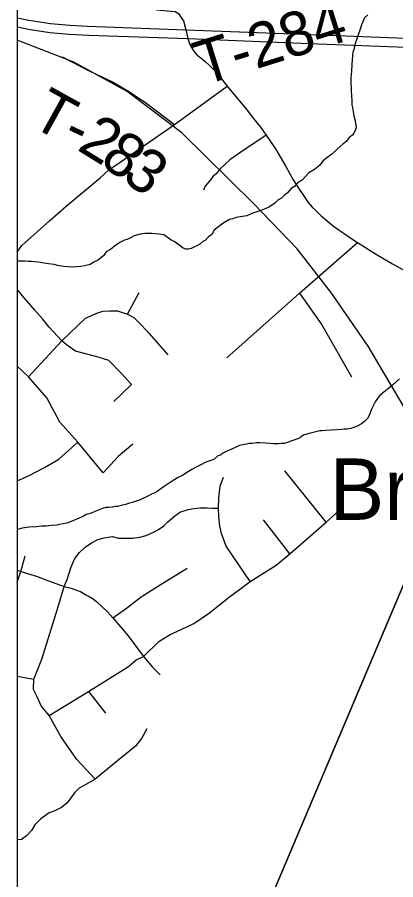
# Model space of a CAD drawing. Extents: x 0 to 34, y 0 to 22.
# Drawn here: x 2.1 to 2.587, y 16.889 to 17.998 of the extents above; entities that cross this region are included whole.
import ezdxf

# ---------------------------------------------------------------- set-up
doc = ezdxf.new("R2010")
doc.units = 0
for name, color, linetype in [('GM_X_Corporation', 7, 'Continuous'), ('GM_X_County_Road', 7, 'Continuous'), ('GM_X_Minor_River', 7, 'Continuous'), ('GM_X_Rail_Line', 7, 'Continuous'), ('GM_X_State_Route', 7, 'Continuous'), ('GM_X_Township_Road', 7, 'Continuous'), ('GM_X_Township_Road_Text', 7, 'Continuous'), ('GM_X_Unincorporated_Text', 7, 'Continuous'), ('SH_Data', 7, 'Continuous')]:
    doc.layers.add(name, color=color, linetype=linetype)

msp = doc.modelspace()

# ---------------------------------------------------------------- linework, layer by layer
at = {"layer": 'GM_X_Corporation'}
for points in [[(2.1, 20.9), (2.1, 16.0934), (2.225, 16.3897), (2.7544, 17.639), (2.811, 17.7726), (2.8255, 17.8068), (2.8709, 17.914), (2.886, 17.9497), (2.8909, 17.9612), (2.9719, 18.1533), (3.7872, 20.088)], [(3.7872, 20.088), (2.9719, 18.1533), (2.8909, 17.9612), (2.886, 17.9497), (2.8709, 17.914), (2.8255, 17.8068), (2.811, 17.7726), (2.7544, 17.639), (2.225, 16.3897), (2.1, 16.0934), (2.1, 14.8365)]]:
    msp.add_lwpolyline(points, dxfattribs=at)
at = {"layer": 'GM_X_County_Road'}
for points in [[(2.1, 18.1121), (2.1218, 18.0985), (2.1562, 18.078), (2.175, 18.0677), (2.2185, 18.0405), (2.228, 18.0349), (2.254, 18.0195), (2.2625, 18.0135), (2.2717, 18.0099), (2.2803, 18.0077), (2.2932, 18.0068), (2.3031, 18.0057), (2.3077, 18.003), (2.3108, 17.9984), (2.314, 17.9938), (2.3172, 17.982), (2.3194, 17.9708)], [(2.3194, 17.9708), (2.3223, 17.9635), (2.3268, 17.9553), (2.3316, 17.9497), (2.3364, 17.9461), (2.3421, 17.9413), (2.3481, 17.9359), (2.3564, 17.9272), (2.3702, 17.9096), (2.3956, 17.8794), (2.4037, 17.8686), (2.413, 17.8569), (2.4205, 17.8468), (2.4324, 17.8291), (2.4456, 17.8064), (2.4552, 17.7893), (2.463, 17.7772), (2.4695, 17.7676), (2.4747, 17.7598), (2.4797, 17.7538), (2.4841, 17.7501), (2.4911, 17.7429), (2.4994, 17.7358), (2.5073, 17.7294), (2.5144, 17.7244), (2.521, 17.7202), (2.5296, 17.7142), (2.538, 17.7083), (2.5633, 17.6925), (2.583, 17.6811), (2.5987, 17.6725)], [(2.1415, 17.7363), (2.1628, 17.7552), (2.2066, 17.7916), (2.2179, 17.8019), (2.2326, 17.8118), (2.3026, 17.8605), (2.3702, 17.9096)], [(2.1, 17.6961), (2.1058, 17.7046), (2.1415, 17.7363)]]:
    msp.add_lwpolyline(points, dxfattribs=at)
at = {"layer": 'GM_X_Minor_River'}
for points in [[(2.5515, 18.0015), (2.5472, 17.9974), (2.5433, 17.9887), (2.5413, 17.9831), (2.5389, 17.9759), (2.536, 17.9668), (2.5341, 17.9619), (2.5336, 17.9577), (2.532, 17.9535), (2.5311, 17.9441), (2.5306, 17.9376), (2.5305, 17.9296), (2.53, 17.9243), (2.5296, 17.9209), (2.5294, 17.9121), (2.5297, 17.9079), (2.5297, 17.9045), (2.5303, 17.8961), (2.5306, 17.8923), (2.5309, 17.8855), (2.5316, 17.8824), (2.5323, 17.8771), (2.533, 17.874), (2.5337, 17.8698), (2.5347, 17.8668), (2.5358, 17.8599), (2.5361, 17.8561), (2.5345, 17.8516), (2.5317, 17.8467), (2.5279, 17.8441), (2.5236, 17.8384), (2.519, 17.8351), (2.512, 17.8284), (2.5051, 17.822), (2.497, 17.8161), (2.4932, 17.8131), (2.4893, 17.8075), (2.4827, 17.8023), (2.4754, 17.7982), (2.4669, 17.7889), (2.4611, 17.7859), (2.4569, 17.7807), (2.4526, 17.7781), (2.4476, 17.7721), (2.4441, 17.7695), (2.4403, 17.7657), (2.436, 17.7632)], [(2.436, 17.7632), (2.4318, 17.759), (2.4249, 17.7546), (2.4191, 17.7517), (2.4134, 17.7495), (2.4084, 17.748), (2.4042, 17.7466), (2.3954, 17.7429), (2.387, 17.7416), (2.3817, 17.7405), (2.3775, 17.7391), (2.3733, 17.738), (2.366, 17.7339), (2.3629, 17.7317), (2.3575, 17.7273), (2.3536, 17.7243), (2.3505, 17.7186), (2.3463, 17.716), (2.342, 17.7112), (2.339, 17.7097), (2.3347, 17.706), (2.324, 17.7008), (2.3205, 17.6998), (2.3171, 17.6998), (2.3137, 17.701), (2.3096, 17.7041), (2.3021, 17.71), (2.2983, 17.7116), (2.2919, 17.7162), (2.2889, 17.7182), (2.2832, 17.7194), (2.2734, 17.72), (2.2642, 17.7201), (2.2581, 17.7191), (2.2505, 17.717), (2.2467, 17.7151), (2.2417, 17.7125), (2.2382, 17.7115), (2.2329, 17.7089), (2.2275, 17.7056), (2.2202, 17.6996), (2.2144, 17.6963), (2.2109, 17.6914), (2.2074, 17.6888), (2.2044, 17.6862), (2.1986, 17.6833), (2.194, 17.6803), (2.1867, 17.6785), (2.1818, 17.6775), (2.1761, 17.6772), (2.1715, 17.6769), (2.1658, 17.677), (2.1597, 17.6778), (2.1518, 17.6787), (2.1476, 17.68), (2.1404, 17.6812), (2.1347, 17.6821), (2.1275, 17.683), (2.1218, 17.6835), (2.1184, 17.6839), (2.1142, 17.684), (2.1097, 17.6844), (2.1059, 17.6845), (2.1, 17.6843)], [(2.5922, 17.533), (2.583, 17.5248), (2.5783, 17.5211), (2.5699, 17.5144), (2.5664, 17.511), (2.5637, 17.5076), (2.5609, 17.5035), (2.5586, 17.499), (2.5562, 17.4941), (2.5542, 17.4892), (2.553, 17.4861), (2.5511, 17.482), (2.5472, 17.4783), (2.543, 17.4753), (2.5376, 17.472), (2.5322, 17.4701), (2.5292, 17.4691), (2.5246, 17.4684), (2.5208, 17.4681), (2.5174, 17.4677), (2.5117, 17.4675), (2.5041, 17.4672), (2.4972, 17.4666), (2.4926, 17.4663), (2.4896, 17.4663), (2.4842, 17.4649), (2.4758, 17.4628), (2.4686, 17.4606), (2.464, 17.4573), (2.4598, 17.4554), (2.4536, 17.4533), (2.4479, 17.4511), (2.4437, 17.45), (2.4399, 17.4497), (2.4365, 17.4494), (2.43, 17.4495), (2.4254, 17.45), (2.4201, 17.4501), (2.4121, 17.4506)], [(2.4121, 17.4506), (2.408, 17.4506), (2.4023, 17.45), (2.3984, 17.4497), (2.395, 17.449), (2.3862, 17.4472), (2.3778, 17.4436), (2.369, 17.4395), (2.3648, 17.4373), (2.3617, 17.4347), (2.3583, 17.434), (2.3529, 17.4292), (2.3429, 17.4259), (2.3364, 17.4226), (2.3303, 17.4193), (2.3249, 17.4163), (2.3191, 17.413), (2.313, 17.4093), (2.3065, 17.4056), (2.2995, 17.4016), (2.2942, 17.3979), (2.2892, 17.3945), (2.2849, 17.3916), (2.2803, 17.3882), (2.2772, 17.3864), (2.273, 17.3846), (2.268, 17.382), (2.2581, 17.3772), (2.2543, 17.3761), (2.2481, 17.374), (2.2447, 17.3729), (2.2394, 17.3714), (2.2336, 17.37), (2.229, 17.369), (2.2256, 17.3686), (2.2226, 17.3679), (2.2176, 17.3676), (2.2142, 17.3673), (2.2096, 17.3663), (2.1989, 17.3619), (2.1951, 17.3604), (2.192, 17.3593), (2.1886, 17.3583), (2.1851, 17.3564), (2.1797, 17.3539), (2.1744, 17.3517), (2.1694, 17.3495), (2.164, 17.3473), (2.1564, 17.3459), (2.1511, 17.3449), (2.1435, 17.3442), (2.1378, 17.3436), (2.1317, 17.3433), (2.1244, 17.3427), (2.1153, 17.3421), (2.1062, 17.3411), (2.1004, 17.3393), (2.1, 17.3392)]]:
    msp.add_lwpolyline(points, dxfattribs=at)
at = {"layer": 'GM_X_Rail_Line'}
msp.add_lwpolyline([(2.7988, 17.139), (2.7752, 17.2035), (2.7136, 17.3012), (2.6321, 17.4391), (2.5518, 17.5749), (2.5037, 17.6444), (2.4602, 17.7003), (2.4041, 17.7589), (2.312, 17.8497), (2.2416, 17.9026), (2.1727, 17.9405), (2.1, 17.969)], dxfattribs=at)
at = {"layer": 'GM_X_State_Route'}
for points in [[(2.1, 17.9977), (2.1151, 17.9948), (2.1428, 17.9904), (2.1678, 17.9882), (2.1903, 17.987), (2.3172, 17.982), (2.4779, 17.976), (2.6115, 17.971), (2.8441, 17.9625), (2.8912, 17.9607), (2.9371, 17.959)], [(2.1, 17.9859), (2.1143, 17.9832), (2.1419, 17.9788), (2.1669, 17.9766), (2.1921, 17.9753), (2.3194, 17.9708), (2.4757, 17.9644), (2.6117, 17.9593), (2.8442, 17.9508), (2.8492, 17.9506)]]:
    msp.add_lwpolyline(points, dxfattribs=at)
at = {"layer": 'GM_X_Township_Road'}
for p, q in [((2.2421, 17.6165), (2.257, 17.6443)), ((2.1145, 17.5357), (2.1, 17.5494)), ((2.4975, 17.3488), (2.4446, 17.4146)), ((2.451, 17.3079), (2.4172, 17.3515)), ((2.1, 17.1505), (2.1212, 17.1467)), ((2.1916, 17.1309), (2.2135, 17.103))]:
    msp.add_line(p, q, dxfattribs=at)
for points in [[(2.1578, 17.9473), (2.1925, 17.9293), (2.2236, 17.9147), (2.2443, 17.9024), (2.267, 17.8874), (2.3026, 17.8605)], [(2.4205, 17.8468), (2.3877, 17.8248), (2.3735, 17.8147), (2.3605, 17.8025), (2.3578, 17.7991)], [(2.3578, 17.7991), (2.3561, 17.797), (2.352, 17.7934), (2.3493, 17.7895), (2.3419, 17.7812), (2.3399, 17.7757)], [(2.3698, 17.5602), (2.4632, 17.6434), (2.538, 17.7083)], [(2.1068, 17.6399), (2.1012, 17.6466), (2.1, 17.6479)], [(2.2245, 17.5038), (2.2471, 17.5258), (2.2347, 17.5393), (2.2178, 17.5565), (2.2042, 17.5608), (2.1831, 17.5665), (2.1752, 17.5686), (2.1632, 17.5767), (2.1572, 17.582), (2.1412, 17.5995), (2.1324, 17.6102), (2.1225, 17.6215), (2.1068, 17.6399)], [(2.4632, 17.6434), (2.4921, 17.6025), (2.5304, 17.5355)], [(2.1145, 17.5357), (2.1572, 17.582), (2.188, 17.6113), (2.2025, 17.6176), (2.2102, 17.6201), (2.2193, 17.6206), (2.229, 17.6206), (2.2421, 17.6165), (2.25, 17.612), (2.2602, 17.6018), (2.2697, 17.5914), (2.2937, 17.564)], [(2.249, 17.4489), (2.2299, 17.4332), (2.2108, 17.4123), (2.1779, 17.4516), (2.155, 17.4771), (2.1379, 17.5088), (2.1145, 17.5357)], [(2.1, 17.4017), (2.1145, 17.4081), (2.1352, 17.4191), (2.1536, 17.4295), (2.1779, 17.4516)], [(2.3999, 17.2721), (2.3688, 17.3179), (2.3631, 17.3341), (2.3607, 17.3441), (2.3593, 17.3557), (2.359, 17.3666), (2.3595, 17.3799), (2.3612, 17.3949), (2.3657, 17.4067)], [(2.2004, 17.0178), (2.1766, 17.0434), (2.1561, 17.0727), (2.1409, 17.0998), (2.131, 17.1125), (2.1255, 17.1238), (2.121, 17.1334), (2.1212, 17.1467), (2.1318, 17.1725), (2.1524, 17.2383), (2.1606, 17.266), (2.1644, 17.2748), (2.1695, 17.291), (2.1743, 17.3019), (2.18, 17.3095), (2.1873, 17.3166), (2.1955, 17.3219), (2.2039, 17.3264), (2.2118, 17.3285), (2.222, 17.33), (2.2304, 17.3279), (2.2396, 17.3282), (2.2482, 17.3282), (2.2579, 17.3295), (2.266, 17.3316), (2.2753, 17.3359), (2.2818, 17.3393), (2.2888, 17.3439), (2.294, 17.3489), (2.3023, 17.3565), (2.3095, 17.3613), (2.32, 17.3649), (2.3275, 17.3663), (2.335, 17.3672), (2.3447, 17.367), (2.3512, 17.3665), (2.359, 17.3666)], [(2.1409, 17.0998), (2.1916, 17.1309), (2.2431, 17.1629), (2.2531, 17.1716), (2.2624, 17.1757), (2.2823, 17.195), (2.2967, 17.2041), (2.311, 17.2105), (2.3275, 17.2182), (2.3476, 17.2319), (2.3717, 17.2511), (2.3894, 17.2645), (2.3999, 17.2721), (2.4333, 17.2935), (2.451, 17.3079), (2.4975, 17.3488), (2.5183, 17.3671)], [(2.1, 17.2716), (2.1048, 17.2851), (2.1101, 17.3052)], [(2.1, 17.2868), (2.1048, 17.2851), (2.1133, 17.2825), (2.126, 17.2788), (2.1354, 17.2749), (2.1606, 17.266), (2.1696, 17.2636), (2.1752, 17.2617), (2.1814, 17.2594), (2.1885, 17.2551), (2.1924, 17.2529), (2.1978, 17.2498), (2.2025, 17.246), (2.2096, 17.2394), (2.2166, 17.2328), (2.223, 17.2255), (2.2426, 17.2025), (2.2624, 17.1757), (2.2743, 17.1622), (2.284, 17.152)], [(2.223, 17.2255), (2.2408, 17.2378), (2.2594, 17.2525), (2.2817, 17.2666), (2.3186, 17.2894)], [(2.267, 17.0827), (2.2601, 17.0704), (2.2523, 17.0604), (2.2223, 17.0358)], [(2.2223, 17.0358), (2.2004, 17.0178), (2.1893, 17.0114), (2.1796, 17.0063), (2.1738, 17.0003), (2.1689, 16.9938), (2.1642, 16.9874), (2.1571, 16.9814), (2.1485, 16.9772), (2.1411, 16.9747), (2.1303, 16.9669), (2.1227, 16.9592), (2.1182, 16.952), (2.1121, 16.945), (2.1055, 16.9405), (2.1, 16.9397)]]:
    msp.add_lwpolyline(points, dxfattribs=at)
at = {"layer": 'SH_Data'}
msp.add_line((2.1, 20.9), (2.1, 14.1), dxfattribs=at)

# ---------------------------------------------------------------- texts
at = {"layer": 'GM_X_Township_Road_Text'}
for s, height, rotation, p in [('T-284', 0.05682, 17.3707, (2.3389, 17.91)), ('T', 0.0568, 331.0328, (2.1149, 17.8601)), ('2', 0.0568, 328.2704, (2.1755, 17.8285)), ('-', 0.0568, 334.9569, (2.1559, 17.8375)), ('8', 0.0568, 324.4781, (2.2044, 17.8106)), ('3', 0.0568, 324.0491, (2.2328, 17.7904))]:
    msp.add_text(s, height=height, rotation=rotation, dxfattribs=at).set_placement(p)
at = {"layer": 'GM_X_Unincorporated_Text'}
msp.add_text('Branch', height=0.07898, rotation=0, dxfattribs=at).set_placement((2.502, 17.3516))

doc.saveas('drawing.dxf')
